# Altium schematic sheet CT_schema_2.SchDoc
size 313 x 200 mm
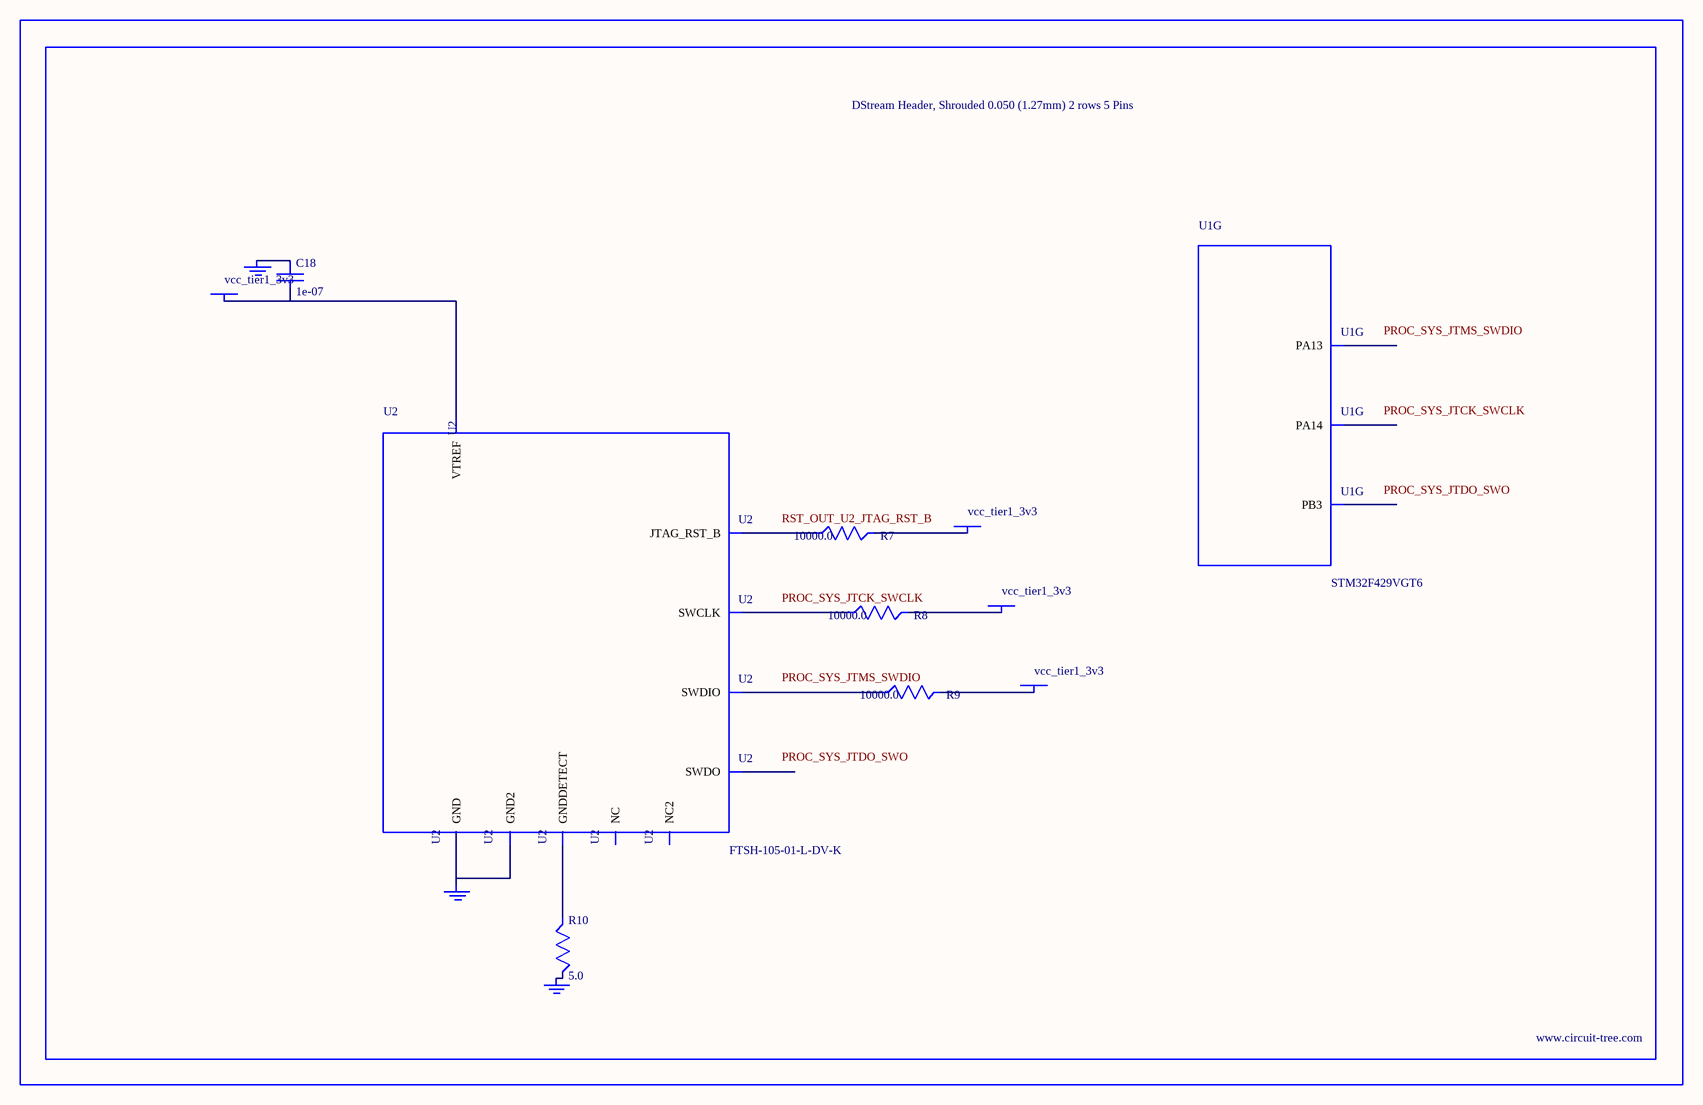
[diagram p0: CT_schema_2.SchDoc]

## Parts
BORDER1  (no value)
C18  1e-07  [C0402]
GND_INSTANCE_1_0  (no value)
GND_INSTANCE_1_1  (no value)
GND_INSTANCE_1_2  (no value)
POWER_INSTANCE_1_0  vcc_tier1_3v3
POWER_INSTANCE_1_1  vcc_tier1_3v3
POWER_INSTANCE_1_2  vcc_tier1_3v3
POWER_INSTANCE_1_3  vcc_tier1_3v3
R7  10000.0  [R0603]
R8  10000.0  [R0603]
R9  10000.0  [R0603]
R10  5.0  [R0603]
U1  STM32F429VGT6  [LQFP100]  (part G of 10)
U2  FTSH-105-01-L-DV-K  [SAMTEC_FTSH-105-01-L-DV-K]

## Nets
NetC18_1: C18.1 GND_INSTANCE_1_0.0(GND)
NetC18_2: C18.2 POWER_INSTANCE_1_0.0(PWR) U2.1(VTREF)
NetGND_INSTANCE_1_1_0: GND_INSTANCE_1_1.0(GND) R10.2
NetGND_INSTANCE_1_2_0: GND_INSTANCE_1_2.0(GND) U2.3(GND) U2.5(GND2)
NetPOWER_INSTANCE_1_1_0: POWER_INSTANCE_1_1.0(PWR) R9.2
NetPOWER_INSTANCE_1_2_0: POWER_INSTANCE_1_2.0(PWR) R8.2
NetPOWER_INSTANCE_1_3_0: POWER_INSTANCE_1_3.0(PWR) R7.2
NetR7_1: R7.1 U2.10(JTAG_RST_B)
NetR8_1: R8.1 U2.4(SWCLK)
NetR9_1: R9.1 U2.2(SWDIO)
NetR10_1: R10.1 U2.9(GNDDETECT)

Not connected (* = marked no-connect by the designer): U1 72(PA13) 76(PA14) 89(PB3); U2 6(SWDO) 7(NC) 8(NC2)

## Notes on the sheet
- Labels drawn without touching a wire or pin: PROC_SYS_JTCK_SWCLK, PROC_SYS_JTDO_SWO, PROC_SYS_JTMS_SWDIO, RST_OUT_U2_JTAG_RST_B

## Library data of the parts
BORDER1 = BORDER_PAGE1
C18 = C0402C104K3RACTU
GND_INSTANCE_1_0-GND_INSTANCE_1_2 = GND
POWER_INSTANCE_1_0-POWER_INSTANCE_1_3 = PWR
R7-R9 = RC0603JR-0710KL
R10 = ERJ-3GEYJ5R1V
